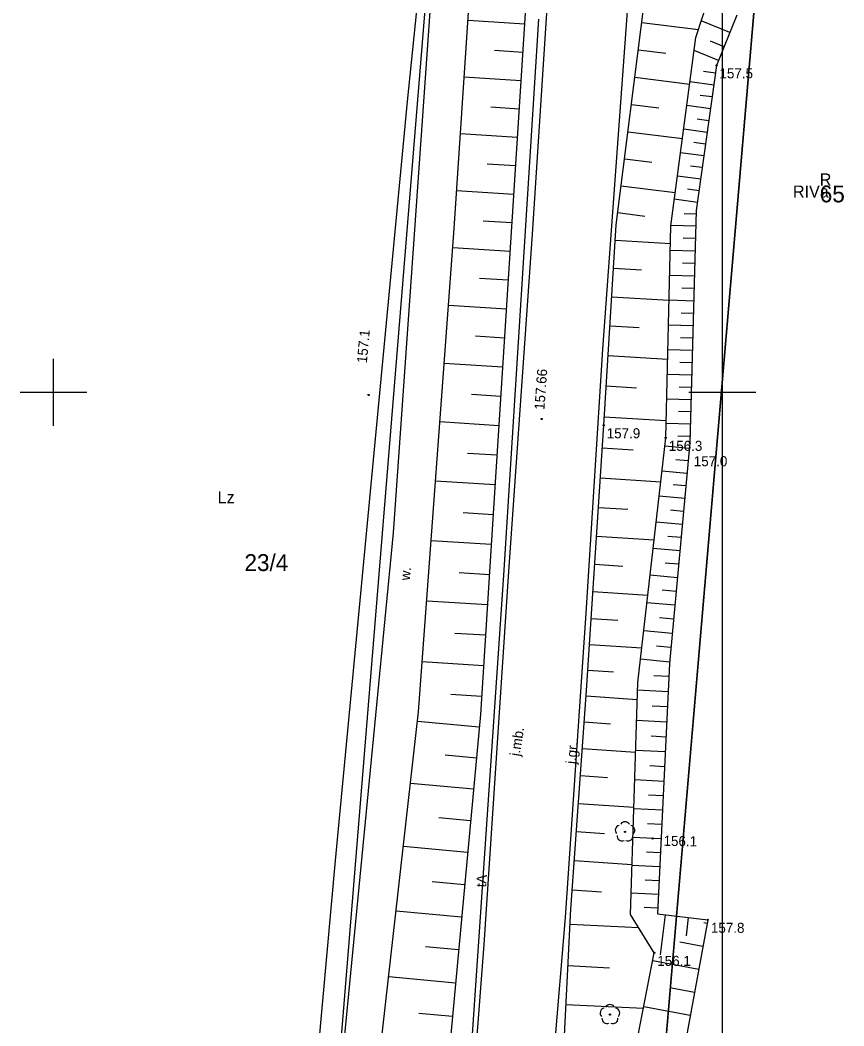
# Model space of a CAD drawing. Extents: x 5598798 to 5599616, y 5661498 to 5662453.
# Drawn here: x 5599147.5 to 5599209.1, y 5661802.6 to 5661877.8 of the extents above; entities that cross this region are included whole.
import ezdxf

# ---------------------------------------------------------------- set-up
doc = ezdxf.new("R2010")
doc.units = 0
for name, color, linetype in [('BUBZ_L_1', 7, 'Continuous'), ('Dzialki', 7, 'Continuous'), ('Kontury', 7, 'Continuous'), ('KTJZ_E_T_0', 7, 'Continuous'), ('KTJZ_L_0', 7, 'Continuous'), ('KTOK_L_4', 7, 'Continuous'), ('Numery_dzialek', 7, 'Continuous'), ('Numery_konturow', 7, 'Continuous'), ('Numery_uzytkow', 7, 'Continuous'), ('OBOP_T_1', 7, 'Continuous'), ('Podzial_sekcyjny_krzyze', 7, 'Continuous'), ('Podzial_sekcyjny_podstawowy', 7, 'Continuous'), ('PTRW_E_T_0', 7, 'Continuous'), ('PTRW_L_1', 7, 'Continuous'), ('RTPW_T_0', 7, 'Continuous'), ('RTPW_T_1', 7, 'Continuous'), ('SUPT_E_T_0', 7, 'Continuous'), ('SUPT_L_0', 7, 'Continuous'), ('Uzytki', 7, 'Continuous')]:
    doc.layers.add(name, color=color, linetype=linetype)

# ---------------------------------------------------------------- blocks, each defined once
blk = doc.blocks.new('2_OBOP02_01')
blk.add_circle((0, 0), 0.045)
for centre, start, end in [((-0.356659, 0.115892), 102.144465, 221.860023), ((0, 0.375056), 30.140124, 149.859876), ((0.356659, 0.115892), 318.139977, 77.855535), ((-0.220404, -0.303384), 174.148182, 293.854228), ((0.220404, -0.303384), 246.145772, 5.851818)]:
    blk.add_arc(centre, 0.375, start, end)
blk = doc.blocks.new('2_RTPW01')
blk.add_circle((0, 0), 0.045)
blk = doc.blocks.new('2_RTPW02')
blk.add_circle((0, 0), 0.045)

msp = doc.modelspace()

# ---------------------------------------------------------------- linework, layer by layer
at = {"layer": 'BUBZ_L_1'}
for p, q in [((5599185.479134, 5661881.732747), (5599182.923041, 5661841.717691)), ((5599198.02, 5661876.51), (5599199.61, 5661881.49)), ((5599179.943143, 5661862.243239), (5599181.124984, 5661879.908151)), ((5599192.07, 5661862.5), (5599194.18, 5661879.24)), ((5599201.09, 5661878.18), (5599199.56, 5661874.43)), ((5599185.209542, 5661877.512346), (5599180.982761, 5661877.782345)), ((5599193.978568, 5661877.641913), (5599198.211064, 5661877.108426)), ((5599200.564958, 5661876.893132), (5599198.421538, 5661877.767648)), ((5599196.14, 5661862.44), (5599198.02, 5661876.51)), ((5599200.1277, 5661875.821422), (5599199.098054, 5661876.241518)), ((5599185.074543, 5661875.398955), (5599182.957969, 5661875.534158)), ((5599193.719675, 5661875.587944), (5599195.773643, 5661875.329051)), ((5599199.707604, 5661874.791776), (5599197.889529, 5661875.53355)), ((5599199.56, 5661874.43), (5599198.05, 5661863.58)), ((5599184.939339, 5661873.282381), (5599180.699817, 5661873.553195)), ((5599193.461742, 5661873.541595), (5599197.55444, 5661873.02573)), ((5599199.478527, 5661873.844583), (5599198.587755, 5661873.968552)), ((5599199.354558, 5661872.95381), (5599197.577869, 5661873.201073)), ((5599199.230927, 5661872.065466), (5599198.345004, 5661872.18876)), ((5599184.803933, 5661871.16262), (5599182.680979, 5661871.29823)), ((5599193.204766, 5661871.502838), (5599195.243524, 5661871.245862)), ((5599199.107632, 5661871.179543), (5599197.340616, 5661871.425459)), ((5599198.984674, 5661870.296035), (5599198.103574, 5661870.418658)), ((5599198.862051, 5661869.414935), (5599197.104654, 5661869.659512)), ((5599184.668322, 5661869.039666), (5599180.41602, 5661869.311296)), ((5599192.948744, 5661869.471643), (5599197.011133, 5661868.959597)), ((5599198.739762, 5661868.536236), (5599197.863459, 5661868.658192)), ((5599192.69367, 5661867.447983), (5599194.71733, 5661867.19291)), ((5599198.617806, 5661867.659933), (5599196.869977, 5661867.903179)), ((5599184.532507, 5661866.913515), (5599182.403154, 5661867.049534)), ((5599198.496183, 5661866.786018), (5599197.624651, 5661866.90731)), ((5599198.374892, 5661865.914486), (5599196.636578, 5661866.156408)), ((5599192.439544, 5661865.43183), (5599196.47185, 5661864.923576)), ((5599198.253931, 5661865.045329), (5599197.387143, 5661865.16596)), ((5599184.396488, 5661864.784161), (5599180.131367, 5661865.05661)), ((5599198.133299, 5661864.178541), (5599196.404449, 5661864.419146)), ((5599192.18636, 5661863.423156), (5599194.195033, 5661863.169972)), ((5599198.04258, 5661863.311655), (5599197.152812, 5661863.336257)), ((5599198.05, 5661863.58), (5599197.57, 5661846.22)), ((5599177.287427, 5661826.126371), (5599179.943143, 5661862.243239)), ((5599184.260263, 5661862.651601), (5599182.124491, 5661862.78803)), ((5599191.13, 5661847.53), (5599192.07, 5661862.5)), ((5599195.76, 5661846.6), (5599196.14, 5661862.44)), ((5599198.017978, 5661862.421887), (5599196.144501, 5661862.473688)), ((5599191.999306, 5661861.374164), (5599196.108241, 5661861.116155)), ((5599197.992078, 5661861.485148), (5599197.055207, 5661861.511053)), ((5599184.123834, 5661860.515829), (5599179.836264, 5661860.789712)), ((5599197.966174, 5661860.548277), (5599196.095858, 5661860.599991)), ((5599191.867753, 5661859.279111), (5599193.962806, 5661859.147558)), ((5599197.940317, 5661859.61312), (5599197.006869, 5661859.638929)), ((5599183.986893, 5661858.372044), (5599181.832809, 5661858.509643)), ((5599197.914507, 5661858.679672), (5599196.051026, 5661858.731197)), ((5599197.888745, 5661857.747932), (5599196.958708, 5661857.773647)), ((5599191.733601, 5661857.142671), (5599196.006481, 5661856.874368)), ((5599197.863029, 5661856.817895), (5599196.006358, 5661856.869232)), ((5599183.849293, 5661856.21796), (5599179.52043, 5661856.494481)), ((5599197.837361, 5661855.88956), (5599196.910723, 5661855.915181)), ((5599191.596799, 5661854.964027), (5599193.775444, 5661854.827225)), ((5599197.81174, 5661854.962921), (5599195.961853, 5661855.01407)), ((5599183.711033, 5661854.053529), (5599181.536204, 5661854.192453)), ((5599197.786165, 5661854.037978), (5599196.862913, 5661854.063506)), ((5599197.760638, 5661853.114726), (5599195.91751, 5661853.165688)), ((5599191.457295, 5661852.742344), (5599195.900661, 5661852.463335)), ((5599183.572109, 5661851.8787), (5599179.201555, 5661852.157883)), ((5599197.735157, 5661852.193162), (5599196.815278, 5661852.218597)), ((5599197.709722, 5661851.273284), (5599195.87333, 5661851.32406)), ((5599191.315034, 5661850.476772), (5599193.580606, 5661850.334512)), ((5599197.684334, 5661850.355088), (5599196.767817, 5661850.380429)), ((5599183.432517, 5661849.693423), (5599181.236742, 5661849.833685)), ((5599197.658993, 5661849.43857), (5599195.829311, 5661849.489161)), ((5599191.169964, 5661848.166445), (5599195.790618, 5661847.876304)), ((5599197.633698, 5661848.523729), (5599196.72053, 5661848.548978)), ((5599183.292255, 5661847.497648), (5599178.879609, 5661847.77952)), ((5599189.84, 5661827.71), (5599191.13, 5661847.53)), ((5599197.608449, 5661847.610561), (5599195.785452, 5661847.660967)), ((5599193.68, 5661828.32), (5599195.76, 5661846.6)), ((5599197.583246, 5661846.699063), (5599196.673415, 5661846.72422)), ((5599191.021066, 5661845.856304), (5599193.331114, 5661845.705953)), ((5599197.530211, 5661845.790908), (5599195.687381, 5661845.961789)), ((5599197.57, 5661846.22), (5599196.04, 5661829.72)), ((5599183.151318, 5661845.291325), (5599180.934397, 5661845.432938)), ((5599197.444771, 5661844.869493), (5599196.513755, 5661844.955823)), ((5599197.358441, 5661843.938477), (5599195.477008, 5661844.112937)), ((5599183.009705, 5661843.074403), (5599178.554562, 5661843.35899)), ((5599190.874263, 5661843.600774), (5599195.385323, 5661843.307168)), ((5599197.271211, 5661842.997761), (5599196.320693, 5661843.0859)), ((5599197.183072, 5661842.047243), (5599195.262229, 5661842.225358)), ((5599182.923041, 5661841.717691), (5599181.907869, 5661825.924682)), ((5599190.730925, 5661841.398475), (5599192.933223, 5661841.255137)), ((5599197.094014, 5661841.086822), (5599196.123586, 5661841.176807)), ((5599182.867064, 5661840.846854), (5599180.629031, 5661840.990714)), ((5599197.004029, 5661840.116394), (5599195.042951, 5661840.298239)), ((5599182.723203, 5661838.608821), (5599178.22653, 5661838.897866)), ((5599190.59097, 5661839.248152), (5599194.891616, 5661838.968241)), ((5599196.913106, 5661839.135854), (5599195.922351, 5661839.227724)), ((5599196.821236, 5661838.145099), (5599194.819079, 5661838.330753)), ((5599190.454317, 5661837.148577), (5599192.553892, 5661837.011925)), ((5599196.728409, 5661837.14402), (5599195.7169, 5661837.237814)), ((5599182.57868, 5661836.360484), (5599180.319993, 5661836.505672)), ((5599196.634615, 5661836.132511), (5599194.590518, 5661836.322054)), ((5599190.32089, 5661835.098554), (5599194.420937, 5661834.831699)), ((5599196.539843, 5661835.110463), (5599195.507146, 5661835.206222)), ((5599182.433492, 5661834.101797), (5599177.895319, 5661834.39351)), ((5599196.444084, 5661834.077765), (5599194.35717, 5661834.271279)), ((5599190.190611, 5661833.096911), (5599192.192254, 5661832.966633)), ((5599196.347327, 5661833.034308), (5599195.292998, 5661833.132073)), ((5599196.249562, 5661831.979979), (5599194.118933, 5661832.177547)), ((5599182.287636, 5661831.83271), (5599180.008103, 5661831.979238)), ((5599190.063407, 5661831.142509), (5599193.972213, 5661830.888101)), ((5599196.150778, 5661830.914665), (5599195.074364, 5661831.014478)), ((5599182.141108, 5661829.553177), (5599177.561052, 5661829.847582)), ((5599196.050965, 5661829.838251), (5599193.875706, 5661830.039957)), ((5599189.939206, 5661829.234231), (5599191.847484, 5661829.110029)), ((5599196.04, 5661829.72), (5599195.14, 5661811.01)), ((5599193.12, 5661810.97), (5599193.68, 5661828.32)), ((5599195.993224, 5661828.747587), (5599194.867103, 5661828.801757)), ((5599188.67, 5661811.36), (5599189.84, 5661827.71)), ((5599195.939055, 5661827.621465), (5599193.660991, 5661827.731046)), ((5599181.993905, 5661827.263149), (5599179.693334, 5661827.411029)), ((5599189.812104, 5661827.320167), (5599193.63889, 5661827.046323)), ((5599172.972858, 5661787.874103), (5599177.287427, 5661826.126371)), ((5599195.884265, 5661826.482433), (5599194.754231, 5661826.536791)), ((5599181.81909, 5661824.964689), (5599177.204531, 5661825.391434)), ((5599181.907869, 5661825.924682), (5599177.972049, 5661783.365144)), ((5599189.672445, 5661825.368529), (5599191.624083, 5661825.22887)), ((5599195.829907, 5661825.3524), (5599193.587697, 5661825.460256)), ((5599195.775979, 5661824.231295), (5599194.663731, 5661824.284797)), ((5599189.529995, 5661823.377882), (5599193.511289, 5661823.092982)), ((5599195.722477, 5661823.119048), (5599193.515557, 5661823.225206)), ((5599181.605718, 5661822.657409), (5599179.275245, 5661822.872927)), ((5599195.669398, 5661822.015588), (5599194.574656, 5661822.068248)), ((5599181.3902, 5661820.326936), (5599176.6824, 5661820.762304)), ((5599189.384698, 5661821.347446), (5599191.415134, 5661821.202149)), ((5599195.616738, 5661820.920846), (5599193.444553, 5661821.025334)), ((5599189.236497, 5661819.276426), (5599193.378537, 5661818.980023)), ((5599195.564494, 5661819.834753), (5599194.486982, 5661819.886585)), ((5599195.512663, 5661818.757242), (5599193.374666, 5661818.860085)), ((5599181.172516, 5661817.973036), (5599178.794954, 5661818.192908)), ((5599189.085333, 5661817.16401), (5599191.197748, 5661817.012847)), ((5599195.461241, 5661817.688243), (5599194.400688, 5661817.739259)), ((5599195.410226, 5661816.627691), (5599193.305879, 5661816.728915)), ((5599180.952644, 5661815.595474), (5599176.149719, 5661816.039639)), ((5599195.359613, 5661815.575517), (5599194.315753, 5661815.625729)), ((5599188.931148, 5661815.009372), (5599193.240424, 5661814.701002)), ((5599195.309401, 5661814.531656), (5599193.238174, 5661814.631288)), ((5599180.730562, 5661813.194011), (5599178.304959, 5661813.418326)), ((5599195.259585, 5661813.496043), (5599194.232154, 5661813.545465)), ((5599188.773881, 5661812.811667), (5599190.971586, 5661812.6544)), ((5599195.210163, 5661812.468612), (5599193.171535, 5661812.566675)), ((5599180.506247, 5661810.768408), (5599175.606275, 5661811.221548)), ((5599187.97, 5661797.77), (5599188.67, 5661811.36)), ((5599195.161131, 5661811.449298), (5599194.149871, 5661811.497942)), ((5599195.14, 5661811.01), (5599198.91, 5661810.57)), ((5599188.613069, 5661810.254733), (5599193.730507, 5661809.991142)), ((5599194.91, 5661808.1), (5599193.12, 5661810.97)), ((5599195.708763, 5661810.943619), (5599195.359056, 5661807.947265)), ((5599198.91, 5661810.57), (5599196.77, 5661798.96)), ((5599197.443365, 5661810.741172), (5599197.283148, 5661809.368403)), ((5599198.861096, 5661810.304684), (5599198.612761, 5661810.350458)), ((5599198.54453, 5661808.58724), (5599196.827086, 5661808.903806)), ((5599180.279677, 5661808.318422), (5599177.805063, 5661808.547269)), ((5599192.92, 5661797.97), (5599194.91, 5661808.1)), ((5599198.227964, 5661806.869797), (5599194.79272, 5661807.502994)), ((5599188.453199, 5661807.150957), (5599191.556975, 5661806.991086)), ((5599180.05083, 5661805.843807), (5599175.051849, 5661806.306103)), ((5599197.911366, 5661805.152175), (5599196.183697, 5661805.470625)), ((5599188.30403, 5661804.254948), (5599194.096047, 5661803.95661)), ((5599179.819682, 5661803.344317), (5599177.295066, 5661803.577788)), ((5599197.592915, 5661803.424506), (5599194.117366, 5661804.065132))]:
    msp.add_line(p, q, dxfattribs=at)
at = {"layer": 'Dzialki'}
for p, q in [((5599170.63, 5661790.83), (5599180.64, 5661913.54)), ((5599202.55, 5661880.8), (5599192.37, 5661761.69))]:
    msp.add_line(p, q, dxfattribs=at)
at = {"layer": 'Kontury'}
msp.add_line((5599192.37, 5661761.69), (5599202.55, 5661880.8), dxfattribs=at)
at = {"layer": 'KTJZ_L_0'}
for p, q in [((5599188.72, 5661906.93), (5599185.78, 5661861.81)), ((5599193.21, 5661882.85), (5599191.03, 5661853.22)), ((5599192.07, 5661862.5), (5599194.18, 5661879.24)), ((5599191.13, 5661847.53), (5599192.07, 5661862.5)), ((5599185.78, 5661861.81), (5599184.01, 5661836.61)), ((5599191.03, 5661853.22), (5599189.78, 5661833.5)), ((5599189.84, 5661827.71), (5599191.13, 5661847.53)), ((5599184.01, 5661836.61), (5599182.17, 5661808.73)), ((5599189.78, 5661833.5), (5599188.25, 5661810.75)), ((5599188.67, 5661811.36), (5599189.84, 5661827.71)), ((5599187.97, 5661797.77), (5599188.67, 5661811.36)), ((5599188.25, 5661810.75), (5599186.15, 5661785.6)), ((5599182.17, 5661808.73), (5599180.02, 5661780.78))]:
    msp.add_line(p, q, dxfattribs=at)
at = {"layer": 'KTOK_L_4'}
for p, q in [((5599180.63, 5661912.77), (5599176.428243, 5661871.738043)), ((5599176.428243, 5661871.738043), (5599171.05222, 5661814.997676)), ((5599171.05222, 5661814.997676), (5599168.830027, 5661790.290817))]:
    msp.add_line(p, q, dxfattribs=at)
at = {"layer": 'Podzial_sekcyjny_krzyze'}
for p, q in [((5599150, 5661847.5), (5599150, 5661852.5)), ((5599200, 5661847.5), (5599200, 5661852.5)), ((5599147.5, 5661850), (5599152.5, 5661850)), ((5599197.5, 5661850), (5599202.5, 5661850))]:
    msp.add_line(p, q, dxfattribs=at)
at = {"layer": 'Podzial_sekcyjny_podstawowy'}
msp.add_line((5599200, 5661750), (5599200, 5662000), dxfattribs=at)
at = {"layer": 'PTRW_L_1'}
for p, q in [((5599178.24884, 5661880.242119), (5599175.395835, 5661839.501206)), ((5599179.943143, 5661862.243239), (5599181.124984, 5661879.908151)), ((5599177.287427, 5661826.126371), (5599179.943143, 5661862.243239)), ((5599175.395835, 5661839.501206), (5599170.668051, 5661790.79835)), ((5599172.972858, 5661787.874103), (5599177.287427, 5661826.126371))]:
    msp.add_line(p, q, dxfattribs=at)
at = {"layer": 'SUPT_L_0'}
for p, q in [((5599186.246732, 5661877.883274), (5599183.629748, 5661836.324248)), ((5599183.629748, 5661836.324248), (5599180.716187, 5661793.727998))]:
    msp.add_line(p, q, dxfattribs=at)
at = {"layer": 'Uzytki'}
for p, q in [((5599170.63, 5661790.83), (5599180.64, 5661913.54)), ((5599202.55, 5661880.8), (5599192.37, 5661761.69))]:
    msp.add_line(p, q, dxfattribs=at)

# ---------------------------------------------------------------- block references
at = {"layer": 'OBOP_T_1'}
for p in [(5599192.72, 5661817.15), (5599191.59, 5661803.49)]:
    msp.add_blockref('2_OBOP02_01', p, dxfattribs=at)
at = {"layer": 'RTPW_T_0', "rotation": -3.0000000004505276e-06}
for p in [(5599199.56, 5661874.43), (5599191.13, 5661847.53), (5599195.76, 5661846.6), (5599197.57, 5661846.22), (5599198.91, 5661810.57), (5599194.91, 5661808.1)]:
    msp.add_blockref('2_RTPW01', p, dxfattribs=at)
at = {"layer": 'RTPW_T_0'}
for p in [(5599173.549943, 5661849.796432), (5599194.782008, 5661816.648334)]:
    msp.add_blockref('2_RTPW01', p, dxfattribs=at)
at = {"layer": 'RTPW_T_1'}
msp.add_blockref('2_RTPW02', (5599186.491799, 5661847.995906), dxfattribs=at)

# ---------------------------------------------------------------- texts
at = {"layer": 'KTJZ_E_T_0'}
for s, rotation, p in [('j.mb.', 81.09999, (5599184.844469, 5661822.76442)), ('j.gr.', 84.299988, (5599189.029408, 5661822.191888))]:
    msp.add_text(s, height=0.75, rotation=rotation, dxfattribs=at).set_placement(p)
at = {"layer": 'Numery_dzialek'}
for s, p in [('65', (5599207.277665, 5661864.190304)), ('23/4', (5599164.26979, 5661836.63803))]:
    msp.add_text(s, height=1.26, dxfattribs=at).set_placement(p)
at = {"layer": 'Numery_konturow'}
msp.add_text('RIVa', height=0.9, dxfattribs=at).set_placement((5599205.273905, 5661864.550304))
at = {"layer": 'Numery_uzytkow'}
for s, p in [('R', (5599207.277665, 5661865.450304)), ('Lz', (5599162.267143, 5661841.70101))]:
    msp.add_text(s, height=0.9, dxfattribs=at).set_placement(p)
at = {"layer": 'PTRW_E_T_0'}
msp.add_text('w.', height=0.75, rotation=85.100896, dxfattribs=at).set_placement((5599176.636982, 5661835.912497))
at = {"layer": 'RTPW_T_0'}
for s, p in [('157.5', (5599199.78, 5661873.46)), ('157.9', (5599191.35, 5661846.56)), ('156.3', (5599195.99, 5661845.62)), ('157.0', (5599197.86, 5661844.47)), ('157.8', (5599199.14, 5661809.6)), ('156.1', (5599195.13, 5661807.13))]:
    msp.add_text(s, height=0.75, dxfattribs=at).set_placement(p)
for s, rotation, p in [('157.1', 84.805558, (5599173.417245, 5661852.15182)), ('156.1', 359.023462, (5599195.593336, 5661816.104241))]:
    msp.add_text(s, height=0.75, rotation=rotation, dxfattribs=at).set_placement(p)
at = {"layer": 'RTPW_T_1'}
msp.add_text('157.66', height=0.75, rotation=85.914371, dxfattribs=at).set_placement((5599186.690846, 5661848.659396))
at = {"layer": 'SUPT_E_T_0'}
msp.add_text('tA', height=0.75, rotation=85.668403, dxfattribs=at).set_placement((5599182.334234, 5661812.983821))

doc.saveas('drawing.dxf')
